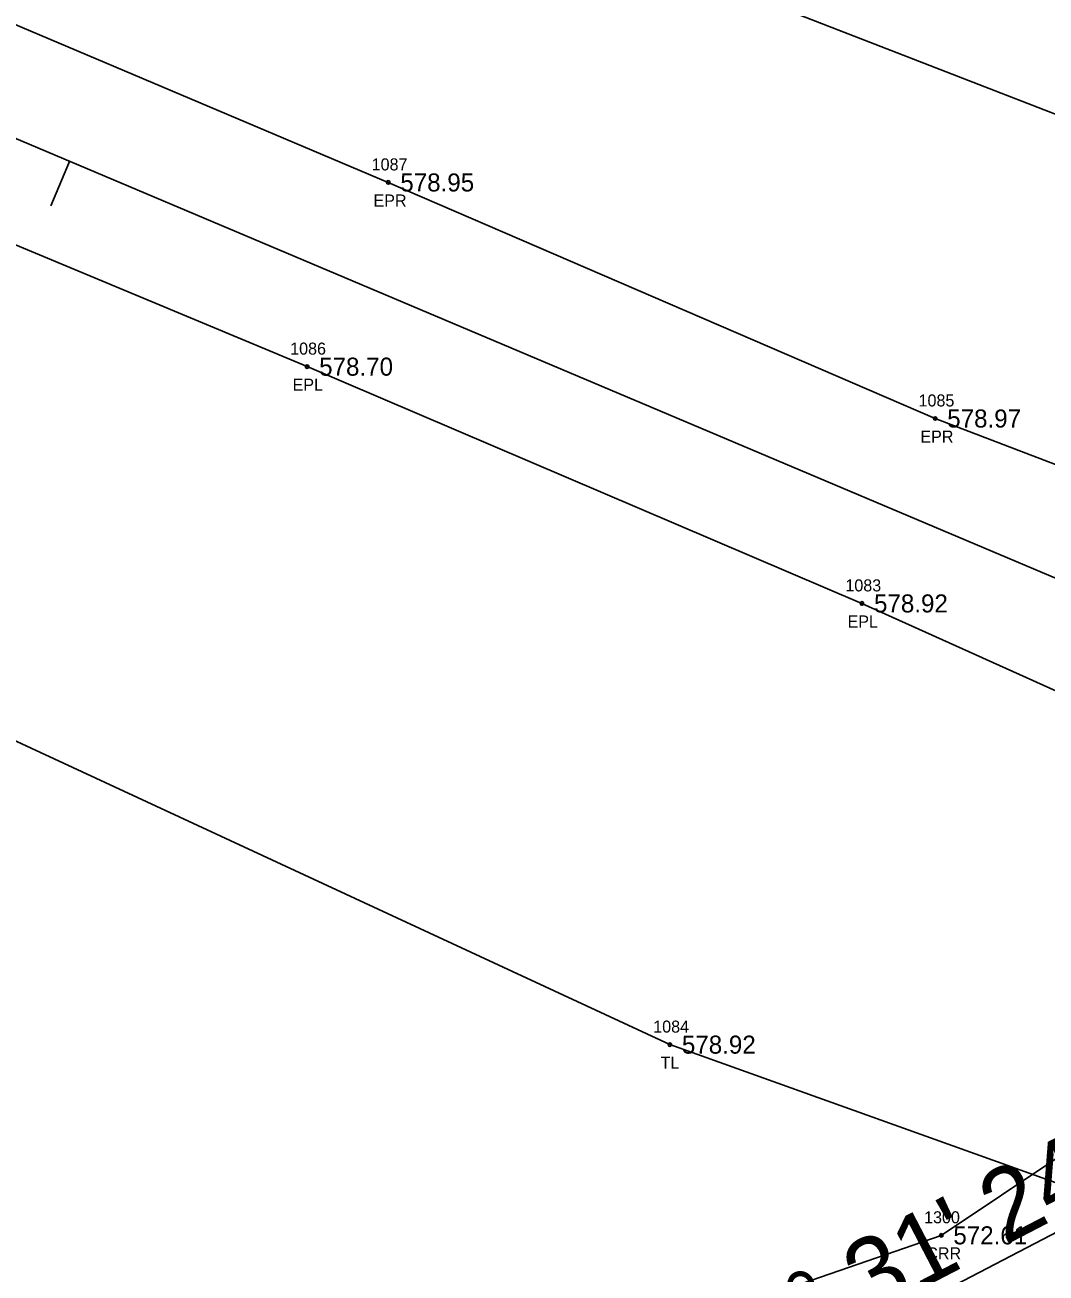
# Model space of a CAD drawing. Extents: x 1664393 to 1667175, y 987029 to 988607.
# Drawn here: x 1665396.3 to 1665481.2, y 987718.5 to 987822.3 of the extents above; entities that cross this region are included whole.
import ezdxf

# ---------------------------------------------------------------- set-up
doc = ezdxf.new("R2010")
doc.units = 0
for name, color, linetype in [('RD_EX_Fence_Other', 7, 'Continuous'), ('RD_EX_H2O', 7, 'Continuous'), ('RD_EX_H2O_txCode', 7, 'Continuous'), ('RD_EX_Road', 7, 'Continuous'), ('RD_EX_Road_txCode', 7, 'Continuous'), ('RD_EX_TX_H2O_ELEV', 7, 'Continuous'), ('RD_EX_TX_Road_ELEV', 7, 'Continuous'), ('RD_EX_TX_VEG_ELEV', 7, 'Continuous'), ('RD_EX_VEG', 7, 'Continuous'), ('RD_EX_VEG_txCode', 7, 'Continuous'), ('RD_HC_Cl', 7, 'Continuous'), ('RD_HC_Data', 7, 'Continuous'), ('RD_HC_Data_Tic', 7, 'Continuous'), ('RD_SMD_Locator', 7, 'Continuous')]:
    doc.layers.add(name, color=color, linetype=linetype)

msp = doc.modelspace()

# ---------------------------------------------------------------- linework, layer by layer
at = {"layer": 'RD_EX_Fence_Other'}
msp.add_lwpolyline([(1665526.5, 987797.57), (1665430.93, 987834.67), (1665344.34, 987868.11), (1665253.91, 987902.76), (1665220.99, 987915.86), (1665222.82, 987921.55)], dxfattribs=at)
at = {"layer": 'RD_EX_H2O'}
msp.add_lwpolyline([(1665506.66, 987778.89), (1665497.35, 987756.86), (1665493.15, 987755.47), (1665489.09, 987748.98), (1665492.34, 987734.97), (1665472.46, 987721.68), (1665444.71, 987712.07), (1665426.39, 987705.52), (1665387.14, 987692.07), (1665353.81, 987678.17), (1665328.18, 987659.89), (1665283.87, 987652.21), (1665224.39, 987676.29), (1665206.47, 987666.98), (1665167.33, 987633.9), (1665123.23, 987629.54), (1665093.05, 987625.54), (1665046.91, 987607.08)], dxfattribs=at)
at = {"layer": 'RD_EX_Road'}
for points in [[(1665506.06, 987776.52), (1665471.95, 987789.57), (1665426.52, 987809.19), (1665380.33, 987828.78), (1665335.61, 987847.53), (1665288.25, 987866.82), (1665242.34, 987886.56), (1665197.07, 987906.16), (1665152.2, 987925.43), (1665127.55, 987936.7), (1665104.5, 987945.2), (1665059.19, 987965.3), (1665013.63, 987984.66), (1664966.38, 988005.06), (1664921.66, 988023.83), (1664875.55, 988043.8)], [(1665498.75, 987759.37), (1665465.87, 987774.2), (1665419.78, 987793.88), (1665373.62, 987813.14), (1665327.95, 987832.31), (1665281.42, 987852.3), (1665236.13, 987871.34), (1665189.6, 987890.71), (1665143.92, 987909.97), (1665117.43, 987920.99), (1665086.22, 987934.27), (1665051.62, 987948.55), (1665005.38, 987968.44), (1664960.17, 987987.67), (1664913.53, 988007.62), (1664868.21, 988026.81)]]:
    msp.add_lwpolyline(points, dxfattribs=at)
at = {"layer": 'RD_EX_VEG'}
msp.add_lwpolyline([(1666150.2, 987465.22), (1665963.16, 987547.12), (1665727.12, 987646.51), (1665543.18, 987704.13), (1665449.91, 987737.53), (1665163.85, 987870.35), (1665156.07, 987854.03)], dxfattribs=at)
at = {"layer": 'RD_HC_Cl'}
for p, q in [((1666160.05, 987489.41), (1664963.07, 987995.8)), ((1665500.02, 987731.29), (1665445.61, 987703))]:
    msp.add_line(p, q, dxfattribs=at)
at = {"layer": 'RD_HC_Data_Tic'}
msp.add_line((1665400.05, 987810.93), (1665398.49, 987807.25), dxfattribs=at)
at = {"layer": 'RD_SMD_Locator'}
for centre in [(1665426.52, 987809.19), (1665419.78, 987793.88), (1665471.95, 987789.57), (1665465.87, 987774.2), (1665449.91, 987737.53), (1665472.46, 987721.68)]:
    msp.add_circle(centre, 0.15, dxfattribs=at)

# ---------------------------------------------------------------- texts
at = {"layer": 'RD_EX_H2O_txCode'}
for s, p in [('1300', (1665471.03, 987722.68)), ('CRR', (1665471.21, 987719.68))]:
    msp.add_text(s, height=1, dxfattribs=at).set_placement(p)
at = {"layer": 'RD_EX_Road_txCode'}
for s, p in [('1087', (1665425.14, 987810.19)), ('EPR', (1665425.29, 987807.19)), ('1086', (1665418.37, 987794.88)), ('EPL', (1665418.57, 987791.88)), ('1085', (1665470.57, 987790.57)), ('EPR', (1665470.72, 987787.57)), ('1083', (1665464.49, 987775.2)), ('EPL', (1665464.67, 987772.2))]:
    msp.add_text(s, height=1, dxfattribs=at).set_placement(p)
at = {"layer": 'RD_EX_TX_H2O_ELEV'}
msp.add_text('572.61', height=1.5, dxfattribs=at).set_placement((1665473.46, 987720.93))
at = {"layer": 'RD_EX_TX_Road_ELEV'}
for s, p in [('578.95', (1665427.52, 987808.44)), ('578.70', (1665420.78, 987793.13)), ('578.97', (1665472.95, 987788.82)), ('578.92', (1665466.87, 987773.45))]:
    msp.add_text(s, height=1.5, dxfattribs=at).set_placement(p)
at = {"layer": 'RD_EX_TX_VEG_ELEV'}
msp.add_text('578.92', height=1.5, dxfattribs=at).set_placement((1665450.91, 987736.78))
at = {"layer": 'RD_EX_VEG_txCode'}
for s, p in [('1084', (1665448.53, 987738.53)), ('TL', (1665449.14, 987735.53))]:
    msp.add_text(s, height=1, dxfattribs=at).set_placement(p)
at = {"layer": 'RD_HC_Data'}
msp.add_text('S 62%%d 31\' 24" W', height=6, rotation=27.4766, dxfattribs=at).set_placement((1665446.99, 987704.84))

doc.saveas('drawing.dxf')
